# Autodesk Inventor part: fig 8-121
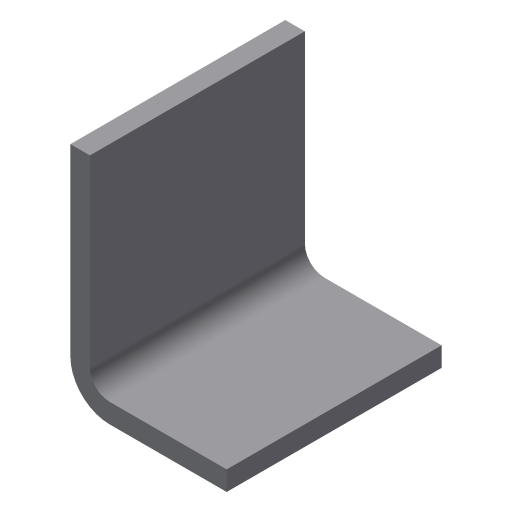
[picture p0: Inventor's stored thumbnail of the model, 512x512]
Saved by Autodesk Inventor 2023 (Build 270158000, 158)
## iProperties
Created: 2009-09
Part Number: fig 8-121
Document SubType Name: Modeling
Designer: Sham
Density: 1 g/cm^3
Material: Generic
Appearance: Default
Author: Sham
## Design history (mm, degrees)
sketch "Sketch1"
  geometry: L1 (-33.976, 22)-(0, 22); L2 (0, 22)-(0, 0); L3 (0, 0)-(-33.976, 0); L4 (-33.976, 0)-(-33.976, 22)
  constraints: 8 end point, 2 parallel, 1 horizontal, 1 perpendicular
extrude "Extrusion1" new body sketch "Sketch1" distance "d0" = 2; taper "d1" = 0 deg
sketch "Sketch2"
  geometry: L1 (-12, 22)-(-12, 0)
  constraints: 2 end point
feature "Bend Part1" sketch "Sketch2" dims "d5" = 90 deg, "d6" = 2
body "Solid1"
